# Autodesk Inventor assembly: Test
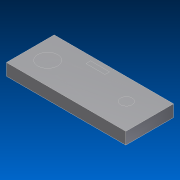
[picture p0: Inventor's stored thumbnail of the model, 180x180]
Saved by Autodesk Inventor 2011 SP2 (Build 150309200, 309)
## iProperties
Created: 2012-03
Part Number: Test
Document SubType Name: Assembly
Designer: BH
Author: BH
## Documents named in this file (5)
- C:\LOKAL_Projekte\FÜ4 HD\intern\Konstruktion\BRG_1\BRG_MW\Test.iam
- C:\LOKAL_Projekte\FÜ4 HD\intern\Konstruktion\BRG_1\BRG_MW\Test1.ipt
- C:\LOKAL_Projekte\FÜ4 HD\intern\Konstruktion\BRG_1\BRG_MW\Test2.ipt
- C:\LOKAL_Projekte\FÜ4 HD\intern\Konstruktion\BRG_1\BRG_MW\Test3.ipt
- C:\LOKAL_Projekte\FÜ4 HD\intern\Konstruktion\BRG_1\BRG_MW\Test123.ipt
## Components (4 placed, 4 different names)
1. Test1:1
2. Test2:1
3. Test3:1
4. Test123:1
